// Mitsubishi GX Works2 project: 40.D0加到D10（循环+变址）   PLC: FX3U/FX3UC

PROGRAM MAIN
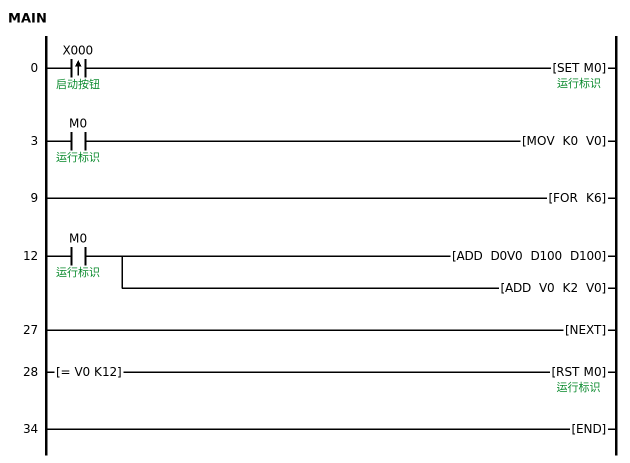
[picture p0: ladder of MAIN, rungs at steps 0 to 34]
0     LDP     X000  ; 启动按钮
      SET     M0  ; 运行标识
3     LD      M0  ; 运行标识
      MOV     K0 V0
9     FOR     K6
12    LD      M0  ; 运行标识
      ADD     D0V0 D100 D100
      ADD     V0 K2 V0
27    NEXT
28    LD=     V0 K12
      RST     M0  ; 运行标识
34    END
END_PROGRAM
